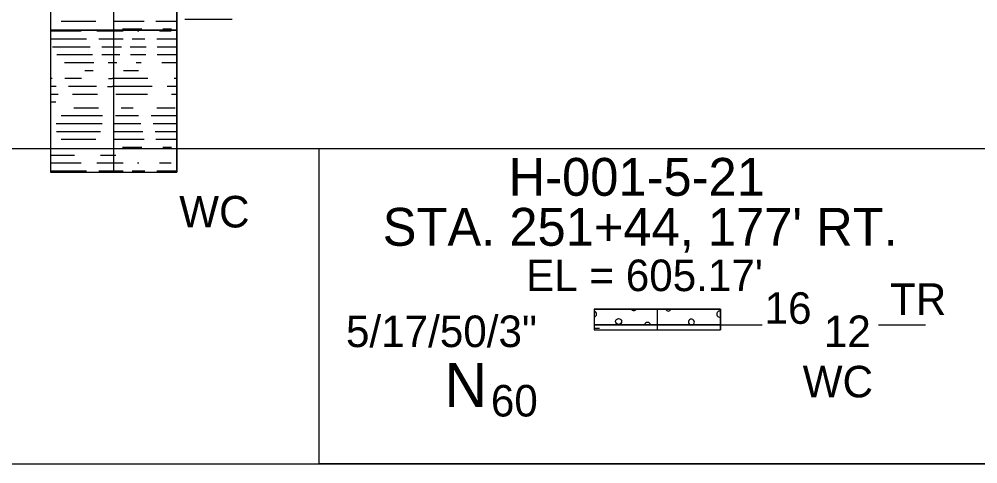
# Model space of a CAD drawing. Extents: x -2280229 to 1306, y -58886 to 440.
# Drawn here: x 316.2 to 377, y 42.2 to 70.4 of the extents above; entities that cross this region are included whole.
import ezdxf

# ---------------------------------------------------------------- set-up
doc = ezdxf.new("R2010")
doc.units = 0
for name, color, linetype in [('BR_P_Sub_Deep_Object', 7, 'Continuous'), ('Default', 7, 'Continuous'), ('GT_Project_Soil_Layers', 7, 'Continuous'), ('SC_Scratch2', 7, 'Continuous'), ('SC_Scratch3', 7, 'Continuous'), ('SC_Scratch4', 7, 'Continuous'), ('SC_Scratch5', 7, 'Continuous'), ('SC_Scratch6', 7, 'Continuous'), ('SC_Scratch9', 7, 'Continuous'), ('SH_Minor_Grid_Line', 7, 'Continuous')]:
    doc.layers.add(name, color=color, linetype=linetype)

msp = doc.modelspace()

# ---------------------------------------------------------------- linework, layer by layer
at = {"layer": 'BR_P_Sub_Deep_Object'}
msp.add_line((326.734, 70.396), (329.734, 70.396), dxfattribs=at)
at = {"layer": 'Default'}
msp.add_lwpolyline([(335.246, 62.208), (384.984, 62.208), (384.984, 42.208), (335.246, 42.208)], close=True, dxfattribs=at)
at = {"layer": 'GT_Project_Soil_Layers'}
for p, q in [((321.099, 70.259), (318.892, 70.259)), ((324.155, 70.259), (322.228, 70.259)), ((326.219, 70.259), (324.893, 70.259)), ((320.169, 69.628), (318.219, 69.628)), ((322.117, 69.628), (321.162, 69.628)), ((322.819, 69.628), (322.117, 69.628)), ((324.016, 69.759), (322.786, 69.759)), ((323.816, 69.628), (323.723, 69.628)), ((325.873, 69.628), (325.137, 69.628)), ((325.89, 69.759), (325.331, 69.759)), ((320.495, 69.128), (318.219, 69.128)), ((322.117, 69.128), (321.287, 69.128)), ((322.827, 69.128), (322.117, 69.128)), ((324.19, 69.128), (323.402, 69.128)), ((326.195, 69.128), (324.959, 69.128)), ((320.726, 68.628), (318.356, 68.628)), ((320.881, 68.128), (318.621, 68.128)), ((322.117, 68.628), (321.48, 68.628)), ((322.117, 68.128), (321.483, 68.128)), ((322.719, 68.628), (322.117, 68.628)), ((322.609, 68.128), (322.117, 68.128)), ((324.292, 68.628), (323.276, 68.628)), ((324.254, 68.128), (323.288, 68.128)), ((326.219, 68.128), (324.97, 68.128)), ((326.219, 68.628), (324.987, 68.628)), ((320.967, 67.628), (319.108, 67.628)), ((322.117, 67.628), (321.87, 67.628)), ((322.43, 67.628), (322.117, 67.628)), ((323.955, 67.628), (323.655, 67.628)), ((326.219, 67.628), (325.269, 67.628)), ((320.918, 67.128), (320.393, 67.128)), ((323.805, 67.128), (322.844, 67.128)), ((318.32, 66.628), (318.219, 66.628)), ((320.188, 66.628), (319.12, 66.628)), ((321.89, 66.628), (322.117, 66.628)), ((324.395, 66.628), (322.117, 66.628)), ((326.219, 66.628), (326.059, 66.628)), ((318.576, 66.128), (318.219, 66.128)), ((318.711, 65.628), (318.219, 65.628)), ((321.128, 66.128), (319.362, 66.128)), ((321.189, 65.628), (319.618, 65.628)), ((321.826, 66.128), (322.117, 66.128)), ((324.655, 66.128), (322.117, 66.128)), ((324.36, 65.628), (322.367, 65.628)), ((326.219, 66.128), (325.611, 66.128)), ((326.219, 65.628), (325.885, 65.628)), ((318.555, 65.128), (318.219, 65.128)), ((321.264, 64.759), (319.695, 64.759)), ((323.463, 64.759), (322.688, 64.759)), ((326.111, 64.759), (324.958, 64.759)), ((321.515, 64.259), (318.898, 64.259)), ((323.797, 64.259), (322.332, 64.259)), ((326.219, 64.259), (324.601, 64.259)), ((321.498, 63.759), (318.587, 63.759)), ((321.394, 63.259), (318.604, 63.259)), ((324.08, 63.259), (322.221, 63.259)), ((323.952, 63.759), (322.283, 63.759)), ((326.219, 63.759), (324.736, 63.759)), ((326.219, 63.259), (324.85, 63.259)), ((321.099, 62.759), (318.892, 62.759)), ((324.155, 62.759), (322.228, 62.759)), ((326.219, 62.759), (324.893, 62.759)), ((324.016, 62.259), (322.786, 62.259)), ((325.89, 62.259), (325.331, 62.259)), ((319.749, 61.759), (318.262, 61.759)), ((322.117, 61.759), (321.394, 61.759)), ((322.356, 61.759), (322.117, 61.759)), ((320.169, 61.259), (318.219, 61.259)), ((320.495, 60.759), (318.219, 60.759)), ((322.117, 61.259), (321.162, 61.259)), ((322.117, 60.759), (321.287, 60.759)), ((322.819, 61.259), (322.117, 61.259)), ((322.827, 60.759), (322.117, 60.759)), ((324.19, 60.759), (323.402, 60.759)), ((323.816, 61.259), (323.723, 61.259)), ((326.195, 60.759), (324.959, 60.759)), ((325.873, 61.259), (325.137, 61.259)), ((353.006, 50.794), (352.67, 50.794))]:
    msp.add_line(p, q, dxfattribs=at)
for points in [[(318.219, 69.693), (326.219, 69.693), (326.219, 75.693), (318.219, 75.693)], [(318.219, 60.693), (326.219, 60.693), (326.219, 69.693), (318.219, 69.693)], [(360.67, 52.009), (352.67, 52.009), (352.67, 51.009), (360.67, 51.009)], [(352.67, 50.709), (360.67, 50.709), (360.67, 51.009), (352.67, 51.009)]]:
    msp.add_lwpolyline(points, close=True, dxfattribs=at)
msp.add_circle((354.221, 51.233), 0.191, dxfattribs=at)
msp.add_circle((354.221, 51.233), 0.191, dxfattribs=at)
for centre, start, end in [((352.63, 51.7), 0, 77.86805), ((352.63, 51.7), 0, 77.86805), ((352.63, 51.7), 282.13195, 0), ((352.63, 51.7), 282.13195, 0), ((355.182, 52.11), 211.95813, 328.04187), ((355.182, 52.11), 211.95813, 328.04187), ((357.372, 52.087), 204.13806, 335.86194), ((357.372, 52.087), 204.13806, 335.86194), ((360.63, 51.7), 77.86805, 282.13195), ((360.63, 51.7), 77.86805, 282.13195), ((356.047, 50.987), 6.6732, 173.3268), ((356.047, 50.987), 6.6732, 173.3268), ((358.835, 51.191), 0, 252.72406), ((358.835, 51.191), 0, 252.72406), ((358.835, 51.191), 287.27594, 0), ((358.835, 51.191), 287.27594, 0)]:
    msp.add_arc(centre, 0.191, start, end, dxfattribs=at)
at = {"layer": 'SC_Scratch2'}
for p, q in [((318.219, 106.693), (318.219, 60.693)), ((322.219, 106.693), (322.219, 60.693)), ((326.219, 106.693), (326.219, 60.693)), ((318.219, 69.693), (326.219, 69.693)), ((318.219, 60.693), (326.219, 60.693)), ((352.67, 52.009), (360.67, 52.009)), ((352.67, 52.009), (352.67, 50.709)), ((356.67, 52.009), (356.67, 50.709)), ((360.67, 52.009), (360.67, 50.709)), ((352.67, 51.009), (360.67, 51.009)), ((352.67, 50.709), (360.67, 50.709))]:
    msp.add_line(p, q, dxfattribs=at)
at = {"layer": 'SC_Scratch3'}
for p, q in [((360.67, 51.009), (363.31, 51.009)), ((370.685, 51.009), (373.67, 51.009)), ((346.127, 47.209), (346.127, 47.209))]:
    msp.add_line(p, q, dxfattribs=at)
at = {"layer": 'SH_Minor_Grid_Line'}
for p, q in [((45.429, 62.208), (603.007, 62.208)), ((45.429, 42.208), (603.007, 42.208))]:
    msp.add_line(p, q, dxfattribs=at)

# ---------------------------------------------------------------- texts
at = {"layer": 'SC_Scratch3'}
for s, height, p in [('H-001-5-21', 2.4, (347.253, 59.199)), ("EL = 605.17'", 2, (348.356, 53.157)), ('N', 2.8, (343.182, 45.809)), ('60', 2, (346.127, 45.209))]:
    msp.add_text(s, height=height, dxfattribs=at).set_placement(p)
at = {"layer": 'SC_Scratch4'}
msp.add_text("STA. 251+44, 177' RT.", height=2.4, dxfattribs=at).set_placement((339.272, 56.032))
at = {"layer": 'SC_Scratch5'}
msp.add_text('5/17/50/3"', height=2, dxfattribs=at).set_placement((336.944, 49.609))
at = {"layer": 'SC_Scratch6'}
for s, p in [('TR', (371.419, 51.649)), ('16', (363.47, 51.083)), ('12', (367.227, 49.609))]:
    msp.add_text(s, height=2, dxfattribs=at).set_placement(p)
at = {"layer": 'SC_Scratch9'}
for p in [(326.376, 57.193), (365.888, 46.421)]:
    msp.add_text('WC', height=2, dxfattribs=at).set_placement(p)

doc.saveas('drawing.dxf')
